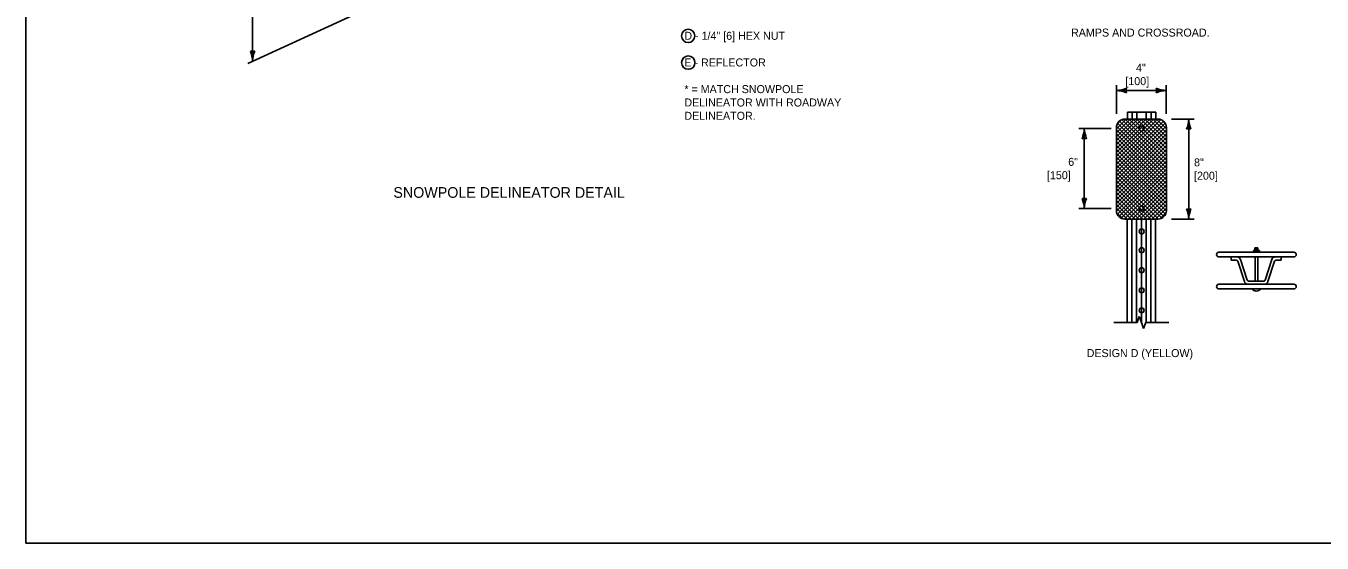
# Model space of a CAD drawing. Extents: x 49991.4 to 50021, y 49987.6 to 50011.4.
# Drawn here: x 49999.38 to 50009.1, y 49987.8 to 49991.68 of the extents above; entities that cross this region are included whole.
import ezdxf

# ---------------------------------------------------------------- set-up
doc = ezdxf.new("R2010")
doc.units = 0
for name, color, linetype in [('Level 1', 7, 'Continuous'), ('Level 2', 7, 'Continuous'), ('Level 3', 7, 'Continuous'), ('Level 5', 7, 'Continuous'), ('Level 6', 7, 'Continuous')]:
    doc.layers.add(name, color=color, linetype=linetype)

msp = doc.modelspace()

# ---------------------------------------------------------------- linework, layer by layer
at = {"layer": 'Level 1'}
for p, q in [((50007.5605, 49990.6691), (50007.8693, 49990.9779)), ((50007.5605, 49990.6985), (50007.8399, 49990.9779)), ((50007.5605, 49990.7279), (50007.8105, 49990.9779)), ((50007.5605, 49990.7573), (50007.7811, 49990.9779)), ((50007.5605, 49990.7867), (50007.7517, 49990.9779)), ((50007.5605, 49990.8163), (50007.7221, 49990.9779)), ((50007.5605, 49990.8457), (50007.6927, 49990.9779)), ((50007.5605, 49990.8751), (50007.6633, 49990.9779)), ((50007.5605, 49990.9045), (50007.6339, 49990.9779)), ((50007.5605, 49990.6397), (50007.8947, 49990.9739)), ((50007.5605, 49990.6103), (50007.9133, 49990.9631)), ((50007.5648, 49990.9382), (50007.6001, 49990.9735)), ((50007.9355, 49990.6103), (50007.5827, 49990.9631)), ((50007.9355, 49990.6397), (50007.6012, 49990.974)), ((50007.873, 49990.9779), (50007.623, 49990.9779)), ((50007.9355, 49990.6691), (50007.6267, 49990.9779)), ((50007.6427, 49991.0286), (50007.8553, 49991.0286)), ((50007.6427, 49990.9779), (50007.6427, 49991.0286)), ((50007.9355, 49990.6985), (50007.6561, 49990.9779)), ((50007.6782, 49990.9779), (50007.6782, 49991.0286)), ((50007.9355, 49990.7279), (50007.6855, 49990.9779)), ((50007.7136, 49990.9779), (50007.7136, 49991.0286)), ((50007.9355, 49990.7573), (50007.7149, 49990.9779)), ((50007.9355, 49990.7867), (50007.7443, 49990.9779)), ((50007.9355, 49990.8163), (50007.7739, 49990.9779)), ((50007.7845, 49990.9779), (50007.7845, 49991.0286)), ((50007.9355, 49990.8457), (50007.8033, 49990.9779)), ((50007.82, 49990.9779), (50007.82, 49991.0286)), ((50007.9355, 49990.8751), (50007.8327, 49990.9779)), ((50007.8553, 49990.9779), (50007.8553, 49991.0286)), ((50007.9355, 49990.9045), (50007.8621, 49990.9779)), ((50007.9311, 49990.9383), (50007.8959, 49990.9735)), ((50007.5605, 49990.5809), (50007.9268, 49990.9472)), ((50007.5605, 49990.5515), (50007.9346, 49990.9256)), ((50007.5605, 49990.9154), (50007.5605, 49990.2904)), ((50007.5605, 49990.5221), (50007.9355, 49990.8971)), ((50007.9355, 49990.5221), (50007.5605, 49990.8971)), ((50007.5605, 49990.4927), (50007.9355, 49990.8677)), ((50007.9355, 49990.4927), (50007.5605, 49990.8677)), ((50007.9355, 49990.5515), (50007.5613, 49990.9257)), ((50007.9355, 49990.5809), (50007.5692, 49990.9472)), ((50007.9355, 49990.2904), (50007.9355, 49990.9154)), ((50007.5605, 49990.4633), (50007.9355, 49990.8383)), ((50007.9355, 49990.4633), (50007.5605, 49990.8383)), ((50007.5605, 49990.4339), (50007.9355, 49990.8089)), ((50007.9355, 49990.4339), (50007.5605, 49990.8089)), ((50007.5605, 49990.4043), (50007.9355, 49990.7793)), ((50007.9355, 49990.4043), (50007.5605, 49990.7793)), ((50007.5605, 49990.3749), (50007.9355, 49990.7499)), ((50007.9355, 49990.3749), (50007.5605, 49990.7499)), ((50007.5605, 49990.3455), (50007.9355, 49990.7205)), ((50007.9355, 49990.3455), (50007.5605, 49990.7205)), ((50007.5605, 49990.3161), (50007.9355, 49990.6911)), ((50007.9355, 49990.3161), (50007.5605, 49990.6911)), ((50007.9354, 49990.2868), (50007.5605, 49990.6617)), ((50007.5606, 49990.2868), (50007.9355, 49990.6617)), ((50007.9294, 49990.2635), (50007.5605, 49990.6323)), ((50007.9172, 49990.2462), (50007.5605, 49990.6029)), ((50007.9, 49990.234), (50007.5605, 49990.5735)), ((50007.5666, 49990.2634), (50007.9355, 49990.6323)), ((50007.5788, 49990.2462), (50007.9355, 49990.6029)), ((50007.596, 49990.234), (50007.9355, 49990.5735)), ((50007.8766, 49990.228), (50007.5605, 49990.5441)), ((50007.8473, 49990.2279), (50007.5605, 49990.5147)), ((50007.8179, 49990.2279), (50007.5605, 49990.4853)), ((50007.6194, 49990.228), (50007.9355, 49990.5441)), ((50007.6487, 49990.2279), (50007.9355, 49990.5147)), ((50007.6781, 49990.2279), (50007.9355, 49990.4853)), ((50007.7885, 49990.2279), (50007.5605, 49990.4559)), ((50007.7591, 49990.2279), (50007.5605, 49990.4265)), ((50007.7295, 49990.2279), (50007.5605, 49990.3969)), ((50007.7001, 49990.2279), (50007.5605, 49990.3675)), ((50007.7075, 49990.2279), (50007.9355, 49990.4559)), ((50007.7369, 49990.2279), (50007.9355, 49990.4265)), ((50007.7665, 49990.2279), (50007.9355, 49990.3969)), ((50007.7959, 49990.2279), (50007.9355, 49990.3675)), ((50007.6707, 49990.2279), (50007.5605, 49990.3381)), ((50007.6413, 49990.2279), (50007.5605, 49990.3087)), ((50007.6106, 49990.2291), (50007.5617, 49990.2782)), ((50007.8253, 49990.2279), (50007.9355, 49990.3381)), ((50007.8547, 49990.2279), (50007.9355, 49990.3087)), ((50007.8853, 49990.2291), (50007.9342, 49990.278)), ((50007.623, 49990.2279), (50007.873, 49990.2279)), ((50007.6413, 49989.453), (50007.6413, 49990.2279)), ((50007.6768, 49989.453), (50007.6768, 49990.2279)), ((50007.7122, 49989.453), (50007.7122, 49990.2279)), ((50007.7831, 49989.453), (50007.7831, 49990.2279)), ((50007.8186, 49989.453), (50007.8186, 49990.2279)), ((50007.8539, 49989.453), (50007.8539, 49990.2271)), ((50008.8914, 49989.9795), (50008.3289, 49989.9795)), ((50008.5886, 49989.993), (50008.633, 49989.993)), ((50008.5886, 49989.993), (50008.5886, 49989.9795)), ((50008.5975, 49990.0114), (50008.6219, 49990.0114)), ((50008.5975, 49989.993), (50008.5975, 49990.0114)), ((50008.5975, 49990.0024), (50008.6219, 49990.0024)), ((50008.6025, 49990.0066), (50008.6185, 49990.0066)), ((50008.6025, 49989.998), (50008.6185, 49989.998)), ((50008.6025, 49989.993), (50008.6025, 49989.9795)), ((50008.6185, 49989.993), (50008.6185, 49989.9795)), ((50008.6219, 49989.993), (50008.6219, 49990.0114)), ((50008.633, 49989.993), (50008.633, 49989.9795)), ((50008.8914, 49989.9443), (50008.3289, 49989.9443)), ((50008.421, 49989.9208), (50008.421, 49989.9443)), ((50008.4637, 49989.9443), (50008.421, 49989.9443)), ((50008.4593, 49989.9208), (50008.421, 49989.9208)), ((50008.52, 49989.7593), (50008.4705, 49989.9126)), ((50008.541, 49989.7707), (50008.4915, 49989.924)), ((50008.6004, 49989.7626), (50008.6004, 49989.9443)), ((50008.6199, 49989.7626), (50008.6199, 49989.9443)), ((50008.6761, 49989.7707), (50008.7255, 49989.924)), ((50008.6971, 49989.7593), (50008.7466, 49989.9126)), ((50008.7534, 49989.9443), (50008.7961, 49989.9443)), ((50008.7961, 49989.9208), (50008.7577, 49989.9208)), ((50008.7961, 49989.9208), (50008.7961, 49989.9443)), ((50008.8914, 49989.7391), (50008.3289, 49989.7391)), ((50008.8914, 49989.7039), (50008.3289, 49989.7039)), ((50008.6649, 49989.7626), (50008.5522, 49989.7626))]:
    msp.add_line(p, q, dxfattribs=at)
msp.add_lwpolyline([(49999.3835, 49998.9992), (50016.7501, 49998.9992), (50016.7501, 49987.7988), (49999.3835, 49987.7988)], close=True, dxfattribs=at)
for centre in [(50007.7495, 49990.9066), (50007.7501, 49990.3071), (50007.7499, 49990.1358), (50007.7499, 49989.9938), (50007.7499, 49989.8438), (50007.7499, 49989.6938), (50007.7499, 49989.5437)]:
    msp.add_circle(centre, 0.0188, dxfattribs=at)
for centre, radius, start, end in [((50007.623, 49990.9154), 0.0625, 90, 180), ((50007.873, 49990.9154), 0.0625, 0, 90), ((50007.623, 49990.2904), 0.0625, 180, 270), ((50007.873, 49990.2904), 0.0625, 270, 0), ((50008.3289, 49989.9619), 0.0176, 90, 270), ((50008.8914, 49989.9619), 0.0176, 270, 90), ((50008.4593, 49989.909), 0.0117, 17.88906, 90), ((50008.4636, 49989.915), 0.0293, 17.88804, 90), ((50008.7533, 49989.915), 0.0293, 90, 162.11105), ((50008.7577, 49989.909), 0.0117, 90, 162.11094), ((50008.3289, 49989.7215), 0.0176, 90, 270), ((50008.5478, 49989.7683), 0.0293, 197.88906, 270), ((50008.5522, 49989.7743), 0.0117, 197.88895, 270), ((50008.6093, 49989.7311), 0.0425, 219.8827, 320.1173), ((50008.6649, 49989.7743), 0.0117, 270, 342.11105), ((50008.6692, 49989.7683), 0.0293, 270, 342.11094), ((50008.8914, 49989.7215), 0.0176, 270, 90)]:
    msp.add_arc(centre, radius, start, end, dxfattribs=at)
at = {"layer": 'Level 2'}
for centre in [(50004.3495, 49991.6013), (50004.3504, 49991.4009)]:
    msp.add_circle(centre, 0.05, dxfattribs=at)
at = {"layer": 'Level 3'}
for p, q in [((50001.0836, 49991.4116), (50001.084, 49993.6622)), ((50001.0472, 49991.3949), (50002.7101, 49992.1589)), ((50007.5605, 49991.0179), (50007.5605, 49991.2321)), ((50007.5605, 49991.1921), (50007.9346, 49991.1921)), ((50007.9346, 49991.0179), (50007.9346, 49991.2321)), ((50007.9746, 49990.9779), (50008.1428, 49990.9779)), ((50008.1028, 49990.9779), (50008.1028, 49990.2279)), ((50007.5205, 49990.9067), (50007.2799, 49990.9067)), ((50007.3199, 49990.9067), (50007.3199, 49990.3072)), ((50007.5205, 49990.3072), (50007.2799, 49990.3072)), ((50007.9746, 49990.2279), (50008.1428, 49990.2279))]:
    msp.add_line(p, q, dxfattribs=at)
for centre, radius, start, end in [((50001.0836, 49991.5398), 0.0548, 252.12861, 287.85097), ((50000.8509, 49991.4002), 0.233, 2.8171, 22.06695), ((50001.3057, 49991.4024), 0.2223, 157.4458, 177.62931), ((50007.549, 49991.4248), 0.233, 272.82731, 292.07716), ((50007.5513, 49990.9699), 0.2223, 67.45601, 87.63952), ((50007.6887, 49991.1921), 0.0548, 162.13882, 197.86118), ((50007.9438, 49991.4142), 0.2223, 247.45601, 267.63952), ((50007.8064, 49991.1921), 0.0548, 342.13882, 17.86118), ((50007.9461, 49990.9593), 0.233, 92.82731, 112.07716), ((50007.8806, 49990.987), 0.2223, 337.45601, 357.63952), ((50008.3355, 49990.9894), 0.233, 182.82731, 202.07716), ((50007.0977, 49990.9158), 0.2223, 337.45601, 357.63952), ((50007.5526, 49990.9182), 0.233, 182.82731, 202.07716), ((50008.1028, 49990.8496), 0.0548, 72.13882, 107.86118), ((50007.3199, 49990.7784), 0.0548, 72.13882, 107.86118), ((50007.3199, 49990.4354), 0.0548, 252.13882, 287.86118), ((50007.0871, 49990.2957), 0.233, 2.82731, 22.07716), ((50007.542, 49990.298), 0.2223, 157.45601, 177.63952), ((50008.1028, 49990.3561), 0.0548, 252.13882, 287.86118), ((50007.87, 49990.2164), 0.233, 2.82731, 22.07716), ((50008.3249, 49990.2187), 0.2223, 157.45601, 177.63952)]:
    msp.add_arc(centre, radius, start, end, dxfattribs=at)
at = {"layer": 'Level 5'}
msp.add_line((50007.7499, 49989.4465), (50007.7499, 49990.2279), dxfattribs=at)
at = {"layer": 'Level 6'}
for p, q in [((50007.7314, 49989.4987), (50007.7152, 49989.453)), ((50007.7314, 49989.4987), (50007.7476, 49989.453)), ((50007.5413, 49989.453), (50007.7152, 49989.453)), ((50007.7476, 49989.453), (50007.7638, 49989.4073)), ((50007.78, 49989.453), (50007.7638, 49989.4073)), ((50007.78, 49989.453), (50007.9539, 49989.453))]:
    msp.add_line(p, q, dxfattribs=at)

# ---------------------------------------------------------------- texts
at = {"layer": 'Level 2'}
for s, height, p in [('D - 1/4" [6] HEX NUT', 0.06, (50004.3207, 49991.5721)), ('RAMPS AND CROSSROAD.', 0.06, (50007.2205, 49991.596)), ('E - REFLECTOR', 0.06, (50004.3207, 49991.3721)), ('4"', 0.06, (50007.7076, 49991.3321)), ('[100]', 0.06, (50007.6278, 49991.2321)), ('* = MATCH SNOWPOLE ', 0.06, (50004.3207, 49991.1721)), ('DELINEATOR WITH ROADWAY', 0.06, (50004.3207, 49991.0721)), ('DELINEATOR.  ', 0.06, (50004.3207, 49990.9721)), ('6"', 0.06, (50007.1992, 49990.6269)), ('8"', 0.06, (50008.1428, 49990.6229)), ('[150]', 0.06, (50007.0394, 49990.5269)), ('[200]', 0.06, (50008.1428, 49990.5229)), ('SNOWPOLE DELINEATOR DETAIL', 0.08, (50002.1388, 49990.3874)), ('DESIGN D (YELLOW)', 0.06, (50007.3376, 49989.1931))]:
    msp.add_text(s, height=height, dxfattribs=at).set_placement(p)

doc.saveas('drawing.dxf')
